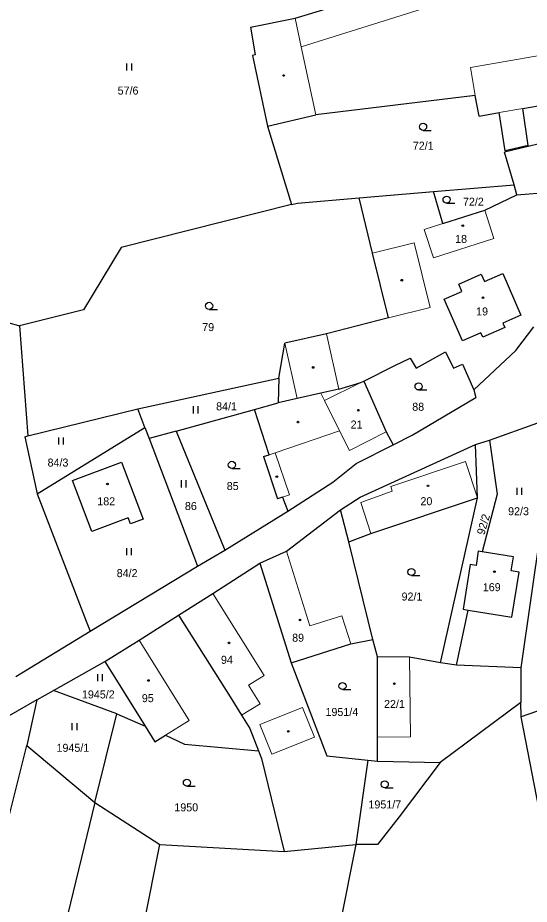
# Model space of a CAD drawing. Extents: x -820420 to -815896, y -1105820 to -1103643.
# Drawn here: x -817820.3 to -817711.7, y -1105107.9 to -1104919.6 of the extents above; entities that cross this region are included whole.
import ezdxf
from ezdxf.enums import TextEntityAlignment as Align

# ---------------------------------------------------------------- set-up
doc = ezdxf.new("R2010")
doc.units = 0
doc.header["$LTSCALE"] = 0.68
for name, color, linetype, lineweight in [('1', 7, 'Continuous', 25), ('3', 7, 'Continuous', 25), ('4', 7, 'Continuous', 13), ('5', 7, 'Continuous', 25)]:
    doc.layers.add(name, color=color, linetype=linetype, lineweight=lineweight)
doc.layers.add('2', color=7, linetype='Continuous')

msp = doc.modelspace()

# ---------------------------------------------------------------- linework, layer by layer
at = {"layer": '1'}
for p, q in [((-817761.4, -1104919.68), (-817732.46, -1104910.88)), ((-817770.87, -1104921.56), (-817761.4, -1104919.68)), ((-817770.87, -1104921.56), (-817769.89, -1104927.45)), ((-817769.89, -1104927.45), (-817770.43, -1104927.6)), ((-817770.43, -1104927.6), (-817767.25, -1104942.6)), ((-817723.12, -1104936.09), (-817757.02, -1104940.22)), ((-817722.33, -1104940.46), (-817723.12, -1104936.09)), ((-817713.03, -1104938.87), (-817708.14, -1104938.03)), ((-817711.88, -1104946.71), (-817713.03, -1104938.87)), ((-817767.25, -1104942.6), (-817757.02, -1104940.22)), ((-817722.33, -1104940.46), (-817718.05, -1104939.73)), ((-817716.8, -1104947.85), (-817718.05, -1104939.73)), ((-817767.25, -1104942.6), (-817762.14, -1104959.27)), ((-817708.08, -1104946.04), (-817716.9, -1104948.13)), ((-817711.88, -1104946.71), (-817716.8, -1104947.85)), ((-817714.89, -1104955.05), (-817716.9, -1104948.13)), ((-817747.81, -1104957.85), (-817731.97, -1104956.5)), ((-817731.97, -1104956.5), (-817714.89, -1104955.05)), ((-817730.04, -1104963.31), (-817731.97, -1104956.5)), ((-817714.27, -1104957.17), (-817714.89, -1104955.05)), ((-817714.27, -1104957.17), (-817706.93, -1104956.61)), ((-817760.92, -1104958.96), (-817747.81, -1104957.85)), ((-817744.93, -1104969.58), (-817747.81, -1104957.85)), ((-817721.13, -1104960.43), (-817714.27, -1104957.17)), ((-817762.14, -1104959.27), (-817798.37, -1104968.37)), ((-817762.14, -1104959.27), (-817760.92, -1104958.96)), ((-817730.04, -1104963.31), (-817721.13, -1104960.43)), ((-817798.37, -1104968.37), (-817806.39, -1104981.6)), ((-817741.56, -1104983.29), (-817744.93, -1104969.58)), ((-817726.64, -1104976.15), (-817721.87, -1104974.05)), ((-817721.87, -1104974.05), (-817721.18, -1104975.61)), ((-817721.18, -1104975.61), (-817717.3, -1104973.91)), ((-817717.3, -1104973.91), (-817713.43, -1104982.74)), ((-817847.04, -1104977.28), (-817819.95, -1104985.04)), ((-817725.96, -1104977.71), (-817726.64, -1104976.15)), ((-817729.73, -1104979.36), (-817725.96, -1104977.71)), ((-817725.81, -1104988.23), (-817729.73, -1104979.36)), ((-817806.39, -1104981.6), (-817819.95, -1104985.04)), ((-817713.43, -1104982.74), (-817717.27, -1104984.47)), ((-817741.56, -1104983.29), (-817754.71, -1104986.72)), ((-817717.27, -1104984.47), (-817716.87, -1104985.38)), ((-817819.95, -1104985.04), (-817818.15, -1105008.41)), ((-817754.71, -1104986.72), (-817763.56, -1104988.7)), ((-817721.96, -1104986.52), (-817725.81, -1104988.23)), ((-817721.55, -1104987.45), (-817721.96, -1104986.52)), ((-817716.87, -1104985.38), (-817721.55, -1104987.45)), ((-817714.53, -1104990.23), (-817710.66, -1104985.25)), ((-817764.87, -1104996.15), (-817763.56, -1104988.7)), ((-817723.43, -1104998.62), (-817714.53, -1104990.23)), ((-817740.23, -1104993.46), (-817736.95, -1104991.86)), ((-817736.95, -1104991.86), (-817735.66, -1104994.03)), ((-817735.66, -1104994.03), (-817729.44, -1104990.58)), ((-817729.44, -1104990.58), (-817727.78, -1104993.99)), ((-817746.77, -1104996.76), (-817740.23, -1104993.46)), ((-817727.78, -1104993.99), (-817725.86, -1104993.19)), ((-817725.86, -1104993.19), (-817723.43, -1104998.62)), ((-817794.83, -1105002.63), (-817764.87, -1104996.15)), ((-817764.87, -1104996.15), (-817764.99, -1105001.41)), ((-817752.08, -1104998.49), (-817747.46, -1104997.04)), ((-817747.46, -1104997.04), (-817746.77, -1104996.76)), ((-817746.77, -1104996.76), (-817742.07, -1105007.56)), ((-817755.93, -1104999.35), (-817760.93, -1105000.47)), ((-817752.08, -1104998.49), (-817755.93, -1104999.35)), ((-817723.43, -1104998.62), (-817722.99, -1105000.28)), ((-817770, -1105002.8), (-817764.99, -1105001.41)), ((-817760.93, -1105000.47), (-817764.99, -1105001.41)), ((-817736.56, -1105008.24), (-817722.99, -1105000.28)), ((-817818.15, -1105008.41), (-817794.83, -1105002.63)), ((-817793.33, -1105006.59), (-817794.83, -1105002.63)), ((-817786.65, -1105007.42), (-817770, -1105002.8)), ((-817766.93, -1105012.42), (-817770, -1105002.8)), ((-817720.13, -1105009.32), (-817709.86, -1105005.6)), ((-817816.2, -1105020.72), (-817793.33, -1105006.59)), ((-817793.33, -1105006.59), (-817792.43, -1105008.97)), ((-817786.65, -1105007.42), (-817792.43, -1105008.97)), ((-817786.65, -1105007.42), (-817776.31, -1105032.67)), ((-817818.79, -1105008.57), (-817818.15, -1105008.41)), ((-817818.79, -1105008.57), (-817816.2, -1105020.72)), ((-817792.43, -1105008.97), (-817782.99, -1105033.83)), ((-817742.07, -1105007.56), (-817740.55, -1105010.27)), ((-817740.55, -1105010.27), (-817736.56, -1105008.24)), ((-817720.13, -1105009.32), (-817718.49, -1105020.77)), ((-817748.44, -1105014.28), (-817740.55, -1105010.27)), ((-817747.61, -1105021.39), (-817723.05, -1105010.23)), ((-817768.1, -1105012.8), (-817766.93, -1105012.42)), ((-817768.1, -1105012.8), (-817765.14, -1105021.8)), ((-817808.67, -1105017.85), (-817798.28, -1105013.95)), ((-817798.28, -1105013.95), (-817793.7, -1105026.08)), ((-817753.37, -1105018.24), (-817748.44, -1105014.28)), ((-817804.58, -1105028.7), (-817808.67, -1105017.85)), ((-817762.92, -1105024.36), (-817753.37, -1105018.24)), ((-817816.2, -1105020.72), (-817805.76, -1105047.76)), ((-817764.07, -1105021.42), (-817765.14, -1105021.8)), ((-817764.07, -1105021.42), (-817762.92, -1105024.36)), ((-817745.29, -1105029.13), (-817722.65, -1105021.53)), ((-817730.5, -1105056.64), (-817722.65, -1105021.53)), ((-817718.49, -1105020.77), (-817721.68, -1105033.04)), ((-817776.31, -1105032.67), (-817762.92, -1105024.36)), ((-817763.25, -1105032.86), (-817751.77, -1105024.12)), ((-817796.9, -1105025.8), (-817804.58, -1105028.7)), ((-817796.39, -1105027.09), (-817796.9, -1105025.8)), ((-817793.7, -1105026.08), (-817796.39, -1105027.09)), ((-817749.99, -1105030.87), (-817745.29, -1105029.13)), ((-817709.27, -1105028.56), (-817713.48, -1105057.68)), ((-817744.86, -1105051.62), (-817749.99, -1105030.87)), ((-817782.99, -1105033.83), (-817782.14, -1105036.08)), ((-817782.14, -1105036.08), (-817776.31, -1105032.67)), ((-817768.9, -1105035.43), (-817763.25, -1105032.86)), ((-817722.49, -1105032.91), (-817722.95, -1105035.91)), ((-817721.68, -1105033.04), (-817722.49, -1105032.91)), ((-817715.03, -1105034.11), (-817721.68, -1105033.04)), ((-817778.91, -1105041.85), (-817768.9, -1105035.43)), ((-817768.9, -1105035.43), (-817762.22, -1105056.59)), ((-817724.18, -1105035.71), (-817725.7, -1105045.23)), ((-817722.95, -1105035.91), (-817724.18, -1105035.71)), ((-817715.51, -1105037.09), (-817715.03, -1105034.11)), ((-817804.95, -1105049.87), (-817782.14, -1105036.08)), ((-817713.83, -1105037.36), (-817715.51, -1105037.09)), ((-817715.35, -1105046.88), (-817713.83, -1105037.36)), ((-817786.14, -1105046.48), (-817778.91, -1105041.85)), ((-817794.54, -1105051.79), (-817786.14, -1105046.48)), ((-817786.14, -1105046.48), (-817775.22, -1105063.83)), ((-817727.08, -1105057.09), (-817724.62, -1105045.4)), ((-817725.7, -1105045.23), (-817724.62, -1105045.4)), ((-817724.62, -1105045.4), (-817715.35, -1105046.88)), ((-817805.76, -1105047.76), (-817804.95, -1105049.87)), ((-817820.71, -1105059.52), (-817804.95, -1105049.87)), ((-817801.83, -1105056.32), (-817794.54, -1105051.79)), ((-817762.22, -1105056.59), (-817749.57, -1105052.54)), ((-817749.57, -1105052.54), (-817744.86, -1105051.62)), ((-817743.87, -1105055.34), (-817744.86, -1105051.62)), ((-817667.12, -1105051.76), (-817713.36, -1105068.05)), ((-817812.71, -1105062.47), (-817801.83, -1105056.32)), ((-817801.83, -1105056.32), (-817793.29, -1105070.06)), ((-817737.08, -1105055.42), (-817743.87, -1105055.34)), ((-817743.87, -1105072.4), (-817743.87, -1105055.34)), ((-817730.5, -1105056.64), (-817737.08, -1105055.42)), ((-817762.22, -1105056.59), (-817754.69, -1105076.38)), ((-817727.08, -1105057.09), (-817730.5, -1105056.64)), ((-817713.48, -1105057.68), (-817727.08, -1105057.09)), ((-817713.48, -1105057.68), (-817713.44, -1105065.06)), ((-817816.27, -1105064.48), (-817812.71, -1105062.47)), ((-817799.24, -1105067.42), (-817812.71, -1105062.47)), ((-817775.22, -1105063.83), (-817772.76, -1105067.74)), ((-817816.27, -1105064.48), (-817860.24, -1105089.62)), ((-817816.27, -1105064.48), (-817818.39, -1105074.2)), ((-817713.44, -1105065.06), (-817730.58, -1105077.81)), ((-817713.36, -1105068.05), (-817713.44, -1105065.06)), ((-817803.95, -1105086.25), (-817799.24, -1105067.42)), ((-817799.24, -1105067.42), (-817793.29, -1105070.06)), ((-817772.76, -1105067.74), (-817771.01, -1105070.52)), ((-817702.55, -1105124.25), (-817713.36, -1105068.05)), ((-817793.29, -1105070.06), (-817791.22, -1105073.39)), ((-817771.01, -1105070.52), (-817769.19, -1105075.3)), ((-817791.22, -1105073.39), (-817788.96, -1105071.98)), ((-817788.96, -1105071.98), (-817784.9, -1105073.87)), ((-817743.87, -1105077.47), (-817743.87, -1105072.4)), ((-817835.64, -1105142.66), (-817818.39, -1105074.2)), ((-817818.39, -1105074.2), (-817803.95, -1105086.25)), ((-817784.9, -1105073.87), (-817769.19, -1105075.3)), ((-817769.19, -1105075.3), (-817768.57, -1105076.92)), ((-817768.57, -1105076.92), (-817763.73, -1105096.71)), ((-817754.69, -1105076.38), (-817745.93, -1105077.26)), ((-817745.93, -1105077.26), (-817748.49, -1105095.18)), ((-817745.93, -1105077.26), (-817743.87, -1105077.47)), ((-817743.87, -1105077.47), (-817730.58, -1105077.81)), ((-817730.58, -1105077.81), (-817739.32, -1105089.29)), ((-817803.95, -1105086.25), (-817821.32, -1105157.54)), ((-817803.95, -1105086.25), (-817790.17, -1105095.18)), ((-817739.32, -1105089.29), (-817743.9, -1105095.16)), ((-817800.7, -1105148.62), (-817790.17, -1105095.18)), ((-817790.17, -1105095.18), (-817763.73, -1105096.71)), ((-817763.73, -1105096.71), (-817748.49, -1105095.18)), ((-817748.49, -1105095.18), (-817752.18, -1105113.44)), ((-817743.9, -1105095.16), (-817748.49, -1105095.18))]:
    msp.add_line(p, q, dxfattribs=at)
for points in [[(-817722.65, -1105021.53), (-817723.05, -1105010.23), (-817720.13, -1105009.32)], [(-817749.99, -1105030.87), (-817751.77, -1105024.12), (-817747.61, -1105021.39)]]:
    msp.add_lwpolyline(points, dxfattribs=at)
at = {"layer": '3'}
for p, q in [((-817797.121, -1104930.77), (-817797.121, -1104929.27)), ((-817796.12, -1104930.77), (-817796.12, -1104929.27)), ((-817734.213, -1104943.5), (-817732.463, -1104943.5)), ((-817729.223, -1104958.96), (-817727.473, -1104958.96)), ((-817779.663, -1104981.53), (-817777.913, -1104981.53)), ((-817735.173, -1104998.65), (-817733.423, -1104998.65)), ((-817782.981, -1105003.61), (-817782.981, -1105002.11)), ((-817781.98, -1105003.61), (-817781.98, -1105002.11)), ((-817811.631, -1105010.24), (-817811.631, -1105008.74)), ((-817810.63, -1105010.24), (-817810.63, -1105008.74)), ((-817774.843, -1105015.3), (-817773.093, -1105015.3)), ((-817785.521, -1105019.34), (-817785.521, -1105017.84)), ((-817784.52, -1105019.34), (-817784.52, -1105017.84)), ((-817714.201, -1105020.91), (-817714.201, -1105019.41)), ((-817713.2, -1105020.91), (-817713.2, -1105019.41)), ((-817797.141, -1105033.74), (-817797.141, -1105032.24)), ((-817796.14, -1105033.74), (-817796.14, -1105032.24)), ((-817736.683, -1105038.07), (-817734.933, -1105038.07)), ((-817803.311, -1105060.5), (-817803.311, -1105059)), ((-817802.31, -1105060.5), (-817802.31, -1105059)), ((-817751.333, -1105062.29), (-817749.583, -1105062.29)), ((-817808.731, -1105070.92), (-817808.731, -1105069.42)), ((-817807.73, -1105070.92), (-817807.73, -1105069.42)), ((-817784.393, -1105082.82), (-817782.643, -1105082.82)), ((-817742.353, -1105083.17), (-817740.603, -1105083.17))]:
    msp.add_line(p, q, dxfattribs=at)
for centre in [(-817734.2129, -1104942.7498), (-817729.2229, -1104958.2098), (-817779.6629, -1104980.7798), (-817735.1729, -1104997.8998), (-817774.8429, -1105014.5498), (-817736.6829, -1105037.3198), (-817751.3329, -1105061.5398), (-817784.3929, -1105082.0698), (-817742.3529, -1105082.4198)]:
    msp.add_circle(centre, 0.75, dxfattribs=at)
at = {"layer": '4'}
for p, q in [((-817731.88, -1104916.91), (-817760.1, -1104925.77)), ((-817761.4, -1104919.68), (-817760.1, -1104925.77)), ((-817760.1, -1104925.77), (-817757.02, -1104940.22)), ((-817698.72, -1104925.76), (-817724.12, -1104930.13)), ((-817723.12, -1104936.09), (-817724.12, -1104930.13)), ((-817718.05, -1104939.73), (-817713.03, -1104938.87)), ((-817721.13, -1104960.43), (-817719.19, -1104966.46)), ((-817733.99, -1104964.59), (-817730.04, -1104963.31)), ((-817733.99, -1104964.59), (-817732.02, -1104970.55)), ((-817744.93, -1104969.58), (-817736.08, -1104967.4)), ((-817719.19, -1104966.46), (-817732.02, -1104970.55)), ((-817754.71, -1104986.72), (-817752.08, -1104998.49)), ((-817763.56, -1104988.7), (-817760.93, -1105000.47)), ((-817755.15, -1105000.91), (-817747.46, -1104997.04)), ((-817755.15, -1105000.91), (-817755.93, -1104999.35)), ((-817755.15, -1105000.91), (-817751.94, -1105007.3)), ((-817749.83, -1105011.51), (-817742.07, -1105007.56)), ((-817766.93, -1105012.42), (-817765.65, -1105012.01)), ((-817765.65, -1105012.01), (-817762.6, -1105020.91)), ((-817741.06, -1105019.18), (-817725.17, -1105013.84)), ((-817722.65, -1105021.53), (-817725.17, -1105013.84)), ((-817747.45, -1105022.58), (-817740.79, -1105020.16)), ((-817740.79, -1105020.16), (-817741.06, -1105019.18)), ((-817762.6, -1105020.91), (-817764.07, -1105021.42)), ((-817745.29, -1105029.13), (-817747.45, -1105022.58)), ((-817758.3, -1105048.75), (-817763.25, -1105032.86)), ((-817778.91, -1105041.85), (-817768.01, -1105059.33)), ((-817751.46, -1105046.59), (-817758.3, -1105048.75)), ((-817749.57, -1105052.54), (-817751.46, -1105046.59)), ((-817794.54, -1105051.79), (-817783.93, -1105068.86)), ((-817737.08, -1105055.42), (-817736.88, -1105072.3)), ((-817768.01, -1105059.33), (-817771.27, -1105061.32)), ((-817771.27, -1105061.32), (-817768.79, -1105065.31)), ((-817768.79, -1105065.31), (-817772.76, -1105067.74)), ((-817759.8, -1105066.06), (-817768.87, -1105069.67)), ((-817759.8, -1105066.06), (-817757.27, -1105072.42)), ((-817783.93, -1105068.86), (-817788.96, -1105071.98)), ((-817768.87, -1105069.67), (-817766.34, -1105076.03)), ((-817757.27, -1105072.42), (-817766.34, -1105076.03)), ((-817736.88, -1105072.3), (-817743.87, -1105072.4))]:
    msp.add_line(p, q, dxfattribs=at)
for points in [[(-817736.08, -1104967.4), (-817732.7, -1104981.12), (-817741.56, -1104983.29)], [(-817765.65, -1105012.01), (-817751.94, -1105007.3), (-817749.83, -1105011.51)]]:
    msp.add_lwpolyline(points, dxfattribs=at)
at = {"layer": '5'}
for centre in [(-817763.8168, -1104931.8492), (-817725.7768, -1104963.7392), (-817738.7368, -1104975.3292), (-817721.4868, -1104979.0692), (-817757.5668, -1104993.8692), (-817747.9768, -1105002.9492), (-817760.7868, -1105005.4792), (-817765.2968, -1105017.0592), (-817801.2668, -1105018.6192), (-817733.1668, -1105019.0092), (-817719.0468, -1105037.2492), (-817760.3768, -1105047.4992), (-817775.4468, -1105052.3692), (-817792.5568, -1105060.3592), (-817740.3068, -1105061.0492), (-817762.8568, -1105071.1692)]:
    msp.add_circle(centre, 0.175, dxfattribs=at)

# ---------------------------------------------------------------- texts
at = {"layer": '2'}
for s, p in [('57/6', (-817796.889, -1104935.905)), ('72/1', (-817734.179, -1104947.615)), ('72/2', (-817723.529, -1104959.505)), ('18', (-817726.139, -1104967.415)), ('19', (-817721.679, -1104982.815)), ('79', (-817779.869, -1104986.145)), ('84/1', (-817775.969, -1105002.975)), ('88', (-817735.249, -1105003.065)), ('21', (-817748.339, -1105006.835)), ('84/3', (-817811.779, -1105014.915)), ('85', (-817774.659, -1105019.905)), ('182', (-817801.529, -1105023.145)), ('86', (-817783.549, -1105024.145)), ('20', (-817733.509, -1105023.125)), ('92/3', (-817713.939, -1105025.255)), ('84/2', (-817797.089, -1105038.405)), ('169', (-817719.629, -1105041.385)), ('92/1', (-817736.569, -1105043.375)), ('89', (-817760.769, -1105052.125)), ('94', (-817775.889, -1105056.815)), ('1945/2', (-817803.21, -1105064.165)), ('95', (-817792.699, -1105064.955)), ('22/1', (-817740.299, -1105066.205)), ('1951/4', (-817751.47, -1105067.895)), ('1945/1', (-817808.61, -1105075.505)), ('1950', (-817784.53, -1105088.155)), ('1951/7', (-817742.34, -1105087.535))]:
    msp.add_text(s, height=1.7, dxfattribs=at).set_placement(p, align=Align.CENTER)
msp.add_text('92/2', height=1.7, rotation=74, dxfattribs=at).set_placement((-817720.5869, -1105027.4278), align=Align.CENTER)

doc.saveas('drawing.dxf')
